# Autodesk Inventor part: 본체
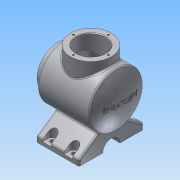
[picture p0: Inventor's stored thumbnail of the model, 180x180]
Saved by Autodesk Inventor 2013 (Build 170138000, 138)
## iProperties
Created: 2017-04
Part Number: 본체
Material: 알루미늄 6061
Document SubType Name: Modeling
Designer: Administrator
Density: 2.71 g/cm^3
Mass: 1692.14 g
Surface Area: 1071.71 cm^2
Volume: 624.405 cm^3
Author: Administrator
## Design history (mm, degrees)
sketch "스케치1"
  geometry: L1 (0, 0)-(120, 0); L2 (0, 0)-(0, 38); L3 (0, 38)-(12, 38); L4 (12, 38)-(12, 50); L5 (12, 50)-(108.336, 50); L6 (0, 27)-(22, 27); L7 (22, 27)-(22, 40); L8 (22, 40)-(101.916, 40); A1 r 113 centre (7, 0) between (120, 0) and (108.336, 50); A2 r 103 centre (7, 0) between (110, 0) and (101.916, 40)
  constraints: 16 end point, 4 parallel, 4 point on circle, 3 perpendicular, 3 point on line, 2 centre point, 1 horizontal
  dimensions: "d0" = 120 distance of L1.start L1.end; "d1" = 113 radius of A1; "d2" = 100 diameter of L5 L1; "d3" = 76 diameter of L3 L1; "d4" = 12 distance of L2.end L3.end; "d5" = 10 radial gap between concentric circles of A1 A2; "d6" = 54 diameter of L6 L1; "d7" = 80 diameter of L8 L1; "d8" = 22 distance of L6.start L6.end
revolve "회전1" sketch "스케치1" stored, may be unused: angle "d9" = 90 deg
node "작업 평면1"
sketch "스케치2"
  geometry: L1 (12, 50)-(108.336, 50) reference; L2 (12, -50)-(12, 50) reference; C1 r 38 at (62, 0); 1 further point
  constraints: 1 centre point, 1 horizontal alignment
  dimensions: "d11" = 76 diameter of C1; "d14" = 50 distance from line of C1.centre L2
extrude "돌출1" join sketch "스케치2" stored distance "d15" = 10; taper "d16" = 0 deg
sketch "스케치3"
  geometry: C1 r 38 at (0, 0) reference; C2 r 27 at (0, 0); 1 further point
  constraints: 1 centre point, 1 coincident
  dimensions: "d17" = 54 diameter of C2
extrude "돌출2" cut sketch "스케치3" distance "d19" = 40; taper "d20" = 0 deg
node "작업 평면4"
  node "작업 평면3"
sketch "스케치4"
  geometry: L1 (-18.364, -42.846)-(-60, -72); L2 (-60, -72)-(-60, -82); L3 (-60, -82)-(60, -82); L4 (60, -82)-(60, -72); L5 (60, -72)-(18.364, -42.846); L6 (-18.364, -42.846)-(18.364, -42.846); C1 r 50 at (0, 0) reference; C2 r 27 at (0, 0) reference; 2 further points
  constraints: 12 end point, 3 perpendicular, 1 midpoint, 1 parallel, 1 vertical, 1 vertical alignment
  dimensions: "d23" = 10 distance of L1.end L2.end; "d25" = 120 distance of L2.end L3.end; "d26" = 55 deg angle of L2 L1; "d27" = 55 deg angle of L4 L5; "d28" = 82 distance from line of L3 point (0, 0)
extrude "돌출3" join sketch "스케치4" distance "d29" = 80; taper "d30" = 0 deg
node "작업 평면5"
sketch "스케치5"
  geometry: L1 (100, 21.584)-(20, 21.584) reference; L2 (100, 60)-(100, 21.584) reference; L3 (20, 60)-(100, 60) reference; L4 (20, 60)-(20, 21.584) reference; L5 (32, 60)-(32, 50); L6 (48, 60)-(48, 50); L7 (72, 60)-(72, 50); L8 (88, 60)-(88, 50); A1 r 8 centre (40, 50) between (32, 50) and (48, 50); A2 r 8 centre (80, 50) between (72, 50) and (88, 50); 1 further point
  constraints: 8 end point, 4 point on circle, 4 point on line, 4 tangent, 3 parallel, 2 centre point, 2 perpendicular, 1 equal radius
  dimensions: "d32" = 8 radius of A1; "d33" = 20 distance from line of L4 A1.centre; "d34" = 10 distance from line of A1.centre L3; "d35" = 20 distance from line of L2 A2.centre
extrude "돌출4" cut sketch "스케치5" distance "d36" = 21; taper "d37" = 0 deg
node "작업 평면6"
node "작업 평면7"
sketch "스케치6"
  geometry: L1 (72, 50)-(72, 60) reference; L2 (88, 60)-(88, 50) reference; L3 (72, 60)-(88, 60) reference; L4 (32, -50)-(32, -60) reference; L5 (48, -60)-(32, -60) reference; L6 (48, -60)-(48, -50) reference; L7 (72, -50)-(72, -60) reference; L8 (88, -60)-(72, -60) reference; L9 (88, -60)-(88, -50) reference; C1 r 4 at (40, 50); C2 r 4 at (80, 50); C3 r 4 at (40, -50); C4 r 4 at (80, -50); A1 r 8 centre (40, 50) between (32, 50) and (48, 50) reference; A2 r 8 centre (80, 50) between (72, 50) and (88, 50) reference; A3 r 8 centre (40, -50) between (48, -50) and (32, -50) reference; A4 r 8 centre (80, -50) between (88, -50) and (72, -50) reference; 1 further point
  constraints: 4 centre point, 4 coincident, 3 equal radius
  dimensions: "d38" = 8 diameter of C1
extrude "돌출5" cut sketch "스케치6" distance "d40" = 20; taper "d41" = 0 deg
sketch "스케치7"
  geometry: L1 (-82, -60)-(-82, 60) reference; C1 r 16 at (-82, 0)
  constraints: 1 centre point, 1 midpoint
  dimensions: "d42" = 32 diameter of C1
extrude "돌출6" cut sketch "스케치7" distance "d44" = 100; taper "d45" = 0 deg
sketch "스케치8"
  geometry: C1 r 38 at (0, 0) reference; C2 r 27 at (0, 0) reference; A1 r 32.5 centre (0, 0) between (32.5, 0) and (0, 32.5); 2 further points
  constraints: 4 point on circle, 2 horizontal alignment, 2 vertical alignment, 1 centre point, 1 coincident
  dimensions: "d46" = 65 diameter of A1
hole "구멍1" sketch "스케치8" at (32.5, 0), (0, 32.5), (-32.5, 0), (0, -32.5) diameter "d49" = 3.242; stored, may be unused: countersink angle "d53" = 90 deg, drill point angle "d55" = 118 deg; dims "d50" = 8, "d51" = 4, "d52" = 2, "d54" = 10
sketch "스케치9"
  geometry: C1 r 27 at (0, 0) reference; C2 r 38 at (0, 0) reference; A1 r 32.5 centre (0, 0) between (0, 32.5) and (-32.5, 0); 3 further points
  constraints: 4 point on circle, 2 horizontal alignment, 2 vertical alignment, 1 centre point, 1 coincident
  dimensions: "d56" = 65 diameter of A1
hole "구멍2" sketch "스케치9" at (0, 32.5), (-32.5, 0), (0, -32.5), (32.5, 0) diameter "d58" = 3.242; stored, may be unused: countersink angle "d62" = 90 deg, drill point angle "d64" = 118 deg; dims "d59" = 8, "d60" = 4, "d61" = 2, "d63" = 10
fillet "모깎기1" dims "d65" = 3
chamfer "모따기1" distance "d66" = 1; stored, may be unused: second distance "d67" = 2, angle "d68" = 45 deg
fillet "모깎기2" dims "d69" = 3
node "작업 평면8"
sketch "스케치10"
  geometry: L1 (60, -82)-(60, -73.562) reference; L2 (-38, 65)-(38, 65) reference; 3 further points
  constraints: 1 coincident, 1 midpoint, 1 vertical alignment, 1 other
feature "엠보싱1" sketch "스케치10" dims "d0" = 120, "d1" = 113, "d2" = 100, "d3" = 76, "d4" = 12, "d5" = 10, "d6" = 54, "d7" = 80, "d8" = 22, "d72" = 0.5, "d73" = 0
fillet "모깎기3" dims "d74" = 3
node "솔리드1"
mirror "대칭1"
node "작업 평면2"
node "투영된 루프1"
node "투영된 루프2"
node "투영된 루프3"
node "투영된 루프4"
node "절단 모서리 투영1"
other parameters: "d10" = 65, "d21" = 6, "d22" = -8, "d31" = -55, "d70" = 132
